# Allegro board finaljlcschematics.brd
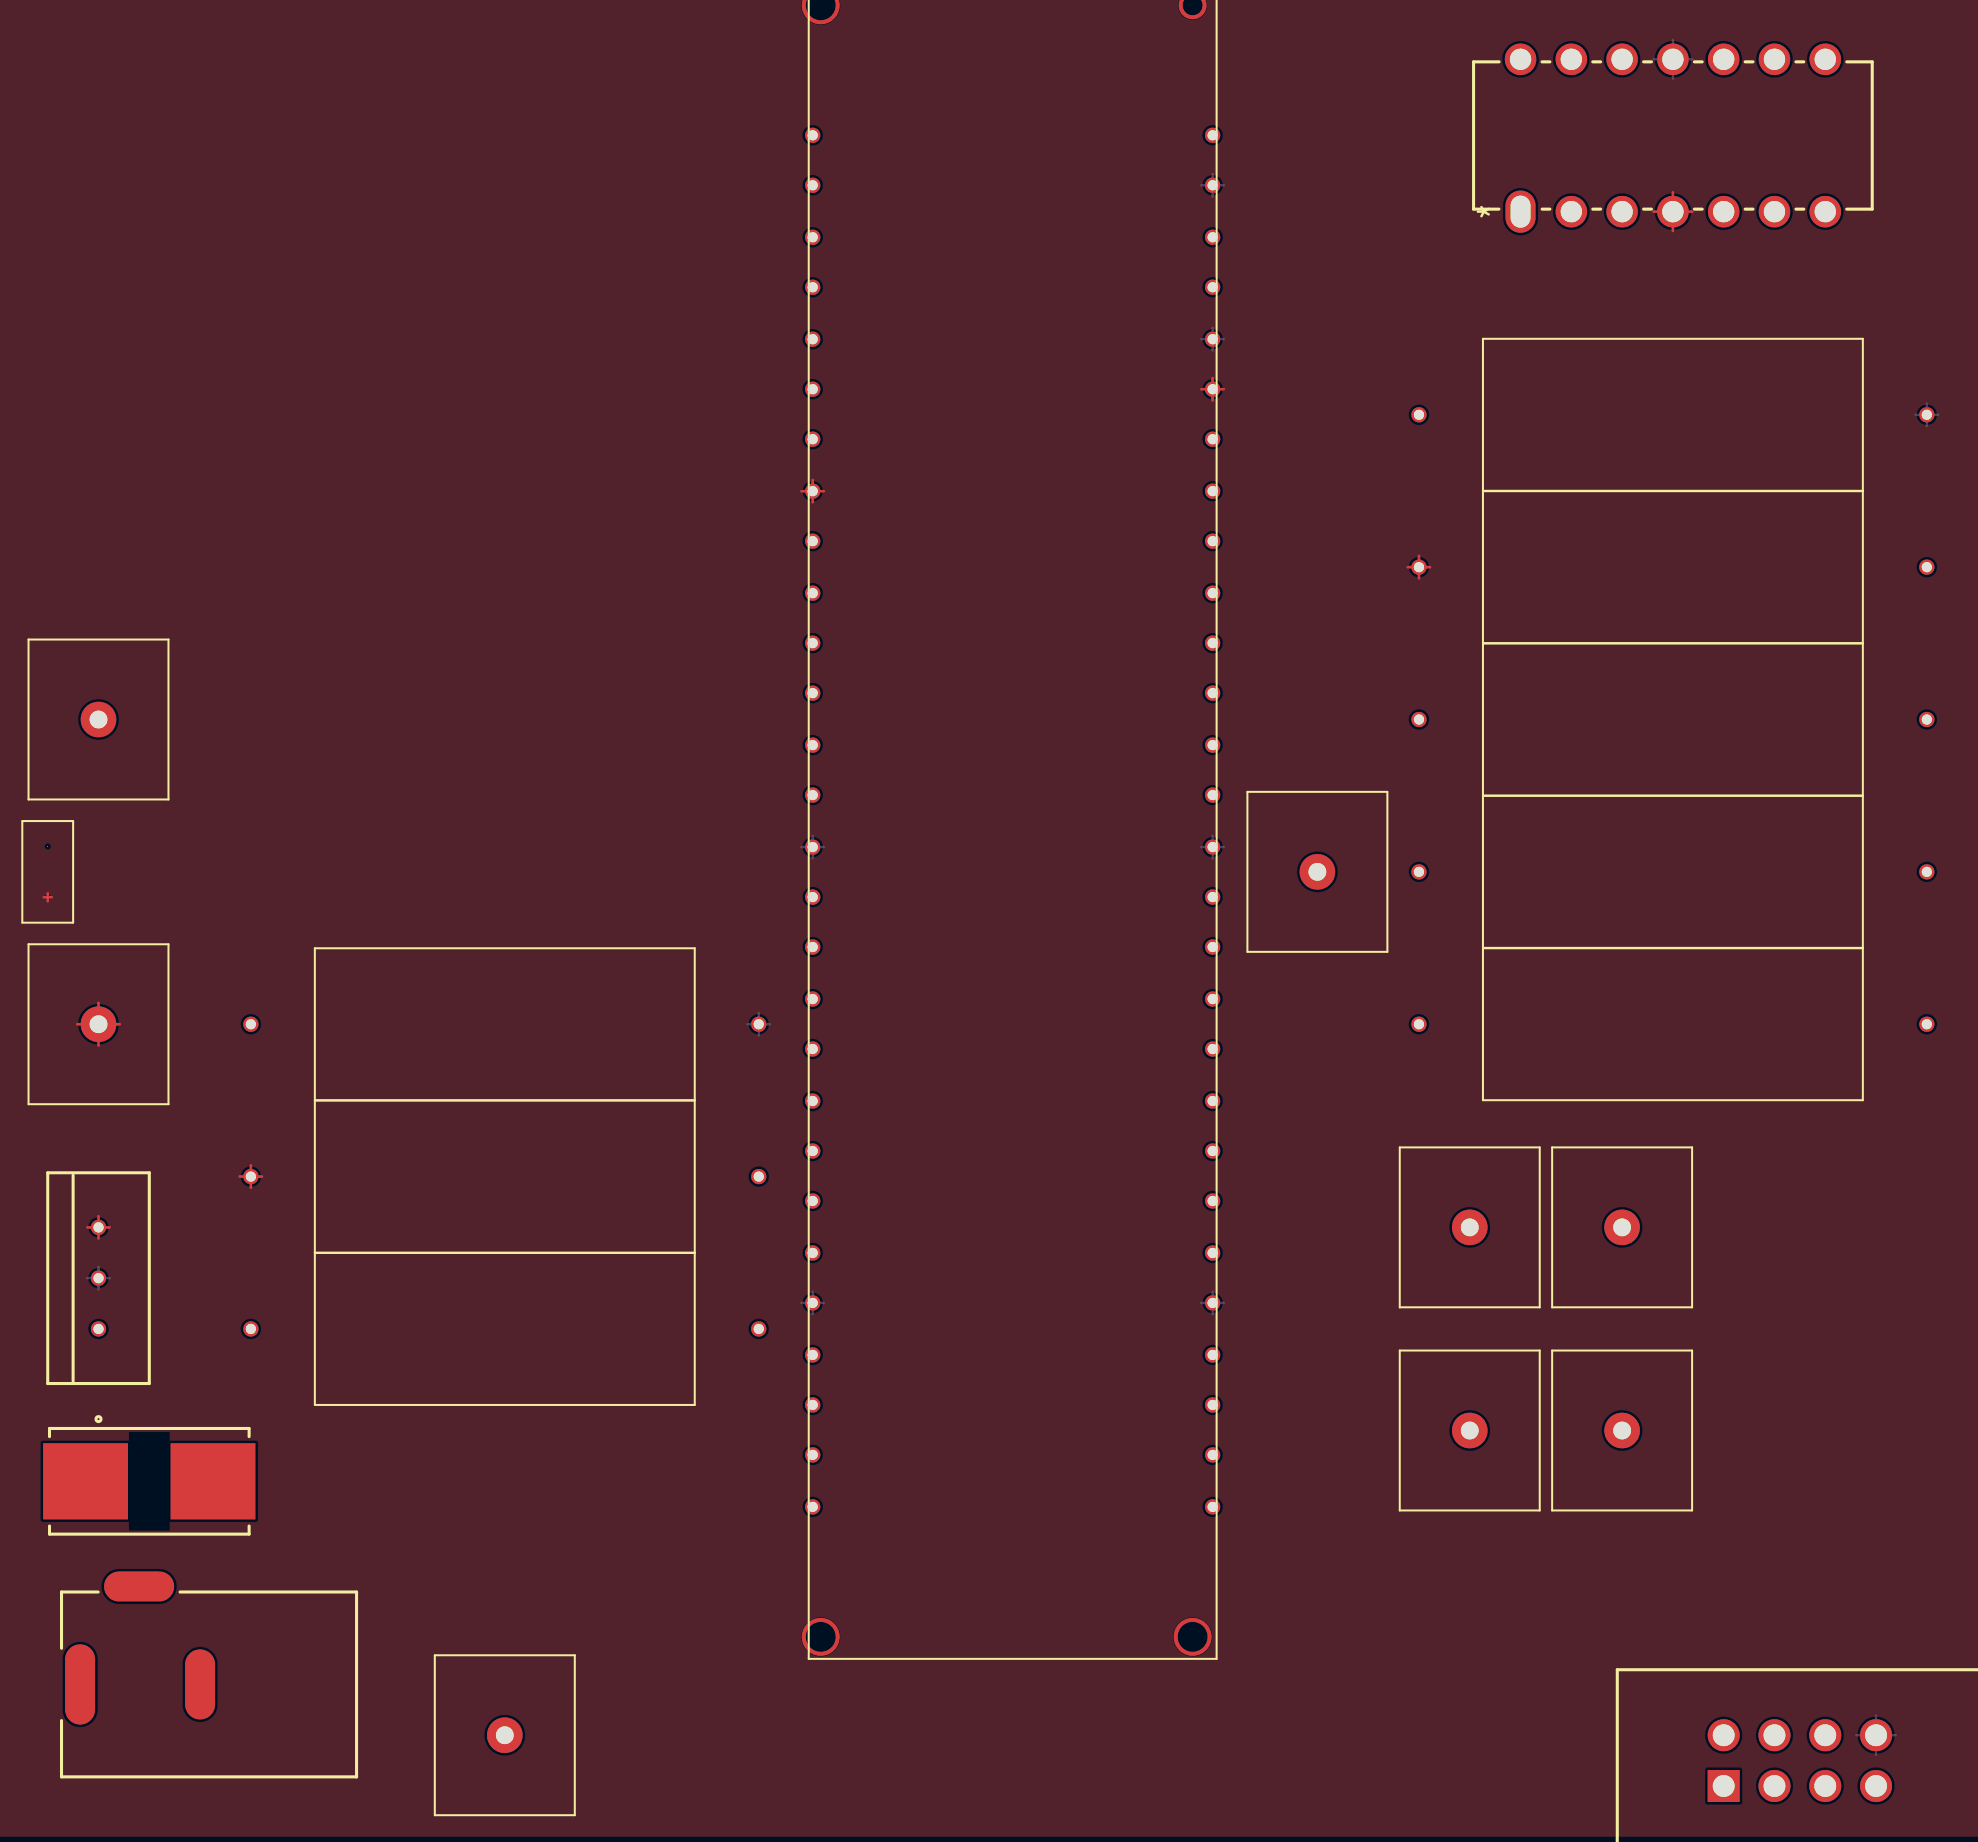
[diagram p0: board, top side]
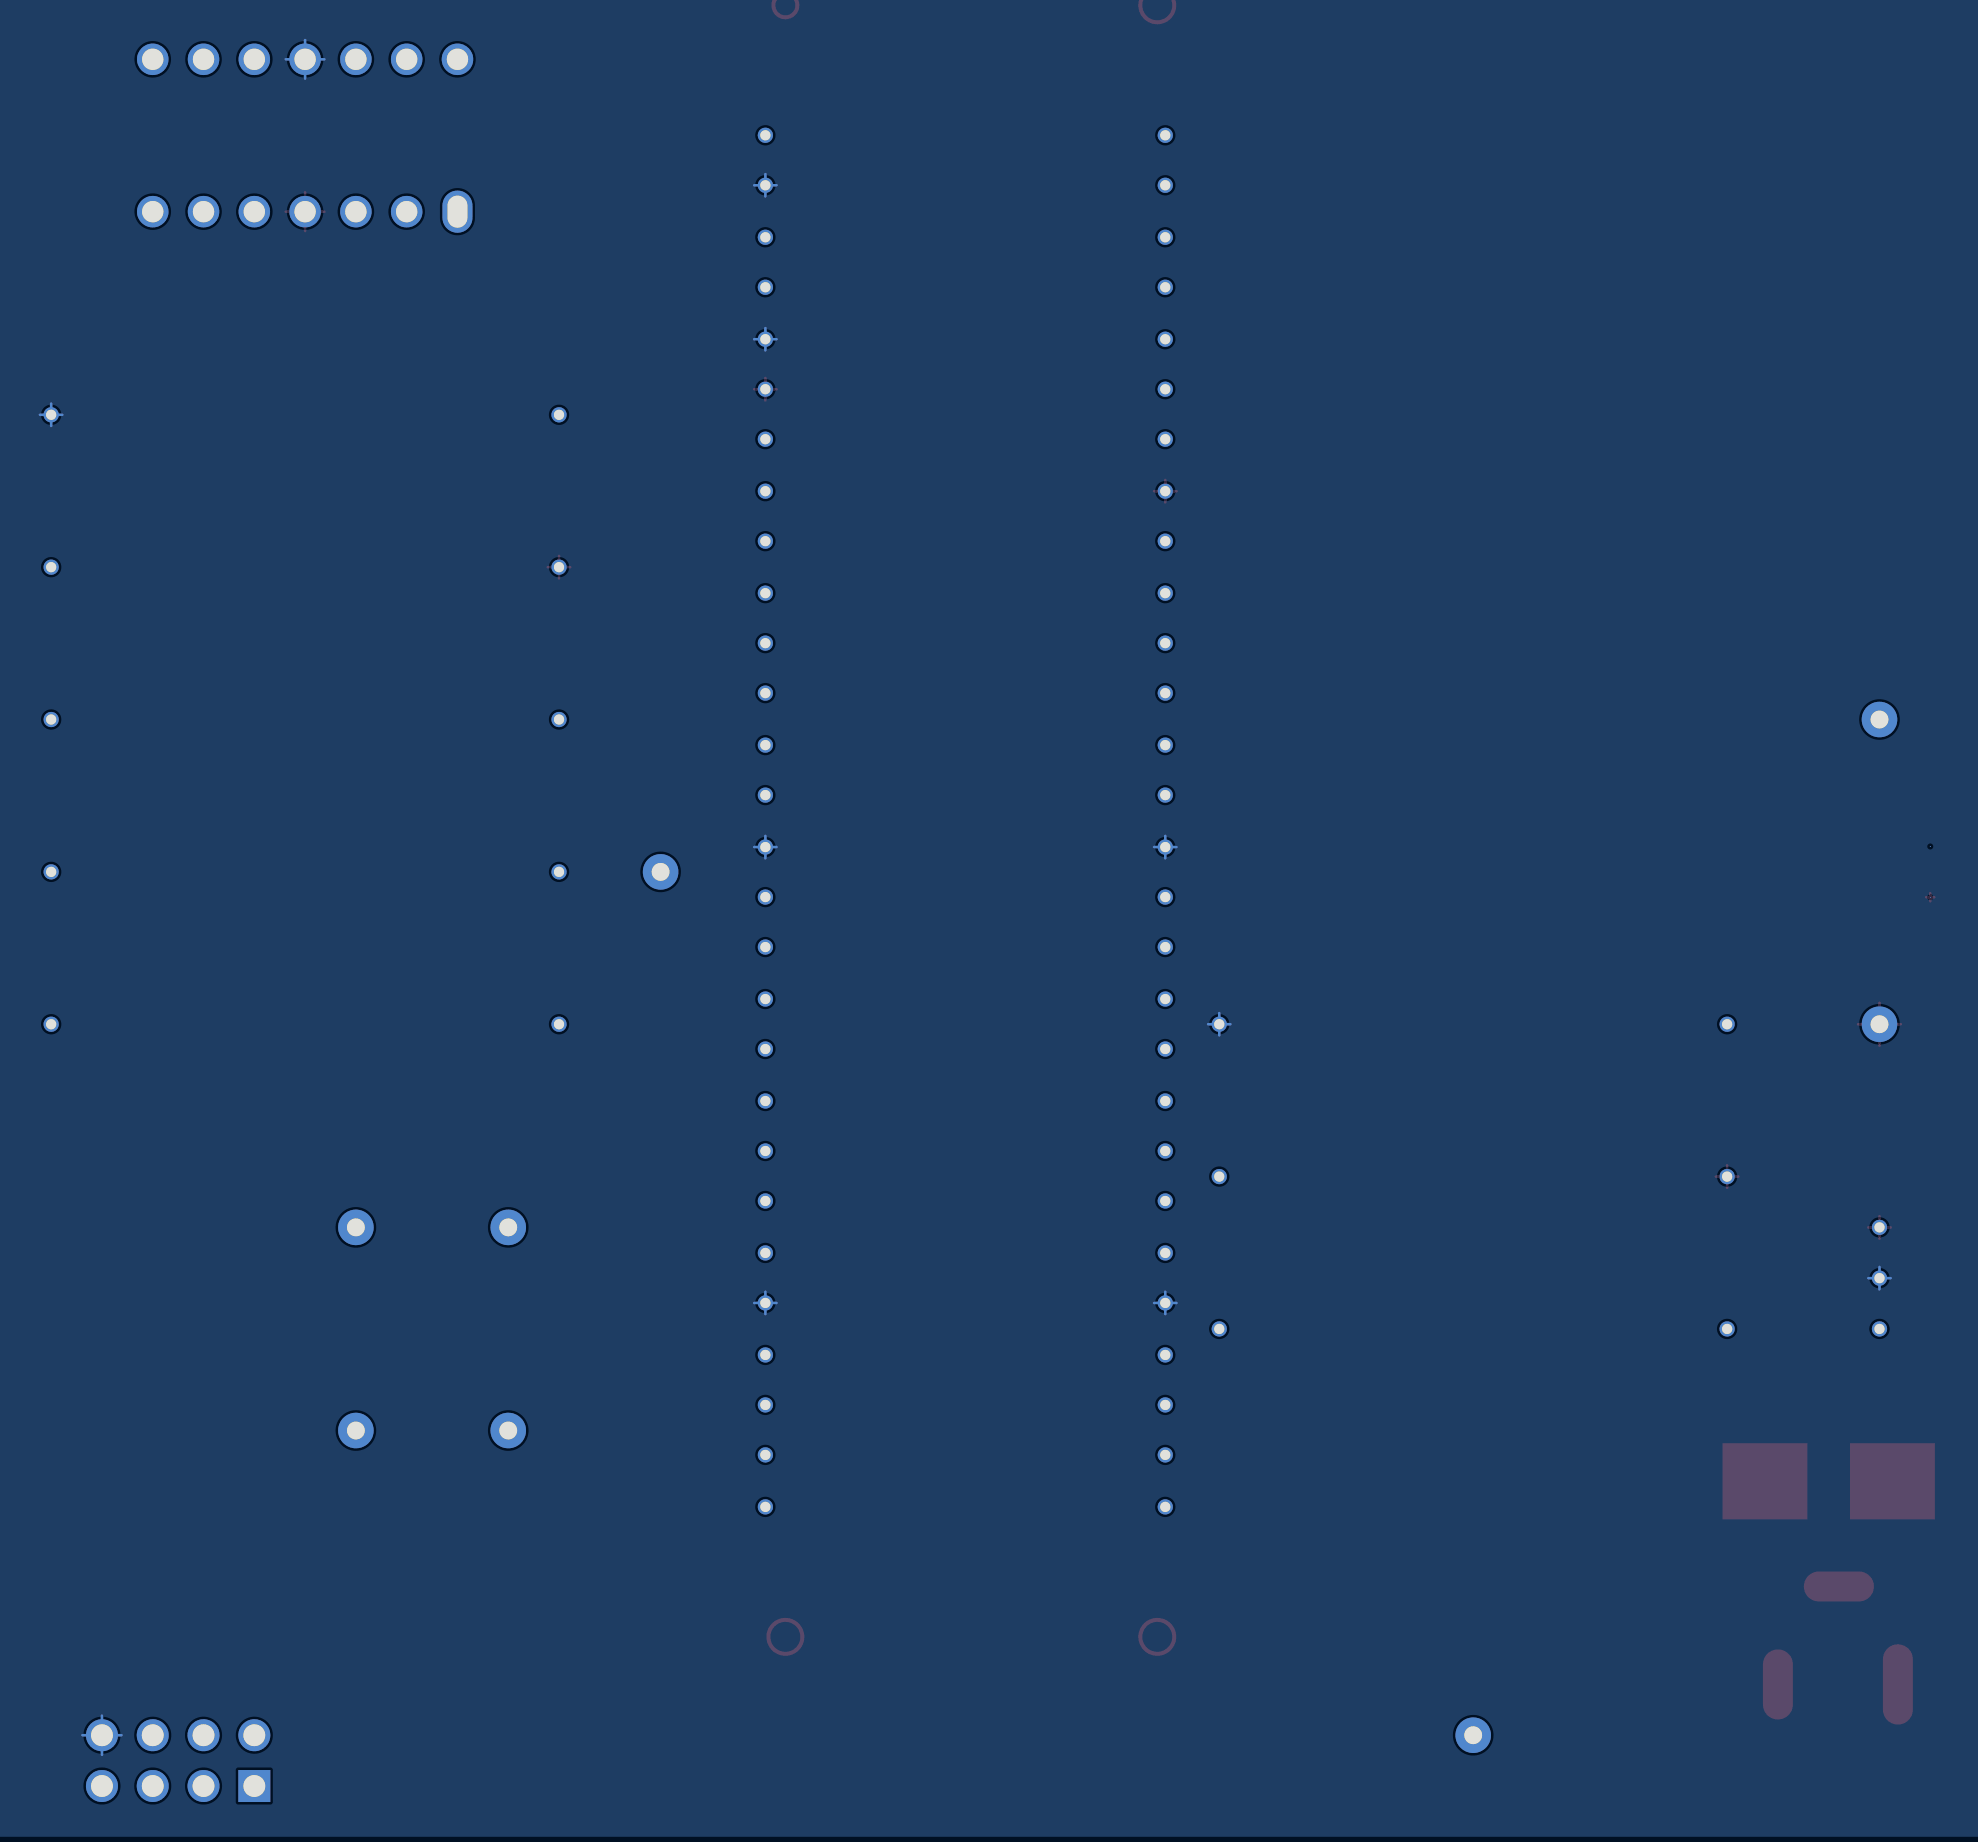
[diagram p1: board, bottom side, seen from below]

No outline. copper layers: TOP, BOTTOM. Coordinates in mm from the lowest, leftmost part position.

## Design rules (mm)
constraint set DEFAULT: min track width 0.127

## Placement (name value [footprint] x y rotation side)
C10  0.1  [RESISTOR_TH]  22.86 22.86 180 top
C11  CAP  [RESISTOR_TH]  22.86 30.48 180 top
F2  FUSE 1.5A  [FUSE_01550900M_LTF]  5.08 15.24 0 top
J22  TestPoint1  [CONNECTORONEPIN]  22.86 2.54 0 top
J23  TestPoint2  [CONNECTORONEPIN]  2.54 38.1 0 top
J25  TestPoint3  [CONNECTORONEPIN]  2.54 53.34 0 top
J27  TestPoint3  [CONNECTORONEPIN]  63.5 45.72 0 top
J29  SpareGPIO1  [CONNECTORONEPIN]  71.12 27.94 0 top
J30  SpareGPIO2  [CONNECTORONEPIN]  71.12 17.78 0 top
J31  SpareGPIO3  [CONNECTORONEPIN]  78.74 27.94 0 top
J32  SpareGPIO4  [CONNECTORONEPIN]  78.74 17.78 0 top
J34  CONN PCB 8_LS  [CONN_61200821621_WRE]  83.82 0 0 top
J35  B_JACK  [NEB21R_LMB]  7.62 5.08 180 top
PCND3  PIC18F57Q43 Curiosity Nano_LS  [56PINS-PIC]  48.26 48.26 0 top
R8  10k  [RESISTOR_TH]  22.86 38.1 0 top
R9  10k  [RESISTOR_TH]  81.28 38.1 0 top
R10  10k  [RESISTOR_TH]  81.28 45.72 0 top
R11  RESISTOR  [RESISTOR_TH]  81.28 53.34 0 top
R12  10k  [RESISTOR_TH]  81.28 60.96 0 top
R13  10k  [RESISTOR_TH]  81.28 68.58 0 top
U11  VR_LS  [TO220-3_ONS]  2.54 22.86 90 top
U12  10kOhms-20kOhms  [HDR_1X02_2]  0 45.72 0 top
U14  MCP6004  [SOIC14-N_MC_MCH]  73.66 78.74 90 top

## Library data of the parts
C10 C11 = MKP1839410084HQ
F2 = FUSE/SM: User Part Number: PN; Tolerance: TOL
J22 J23 J25 J27 J29-J32 = CON1
J34 = CONN PCB 8_2: User Part Number: PN; Tolerance: TOL
J35 = B_JACK: User Part Number: PN; Tolerance: TOL
PCND3 = PIC18F57Q10_18
R8-R13 = RESISTOR
U11 = VR_LS_11: User Part Number: PN; Tolerance: TOL
U12 = FLEX_SENSOR_FS_L_095_103_RH_0
U14 = MCP6004_0: User Part Number: PN; Tolerance: TOL

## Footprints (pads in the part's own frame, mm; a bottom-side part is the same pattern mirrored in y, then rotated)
56PINS-PIC
  round 0.762 hole 0.508: 1(-10,34.3) 2(-10,31.8) 3(-10,29.2) 4(-10,26.7) 5(-10,24.1) 6(-10,21.6) 7(-10,19.1) 8(-10,16.5) 9(-10,14) 10(-10,11.4) 11(-10,8.9) 12(-10,6.4) 13(-10,3.8) 14(-10,1.3) 15(-10,-1.3) 16(-10,-3.8) 17(-10,-6.3) 18(-10,-8.9) 19(-10,-11.4) 20(-10,-14) 21(-10,-16.5) 22(-10,-19) 23(-10,-21.6) 24(-10,-24.1) 25(-10,-26.7) 26(-10,-29.2) 27(-10,-31.7) 28(-10,-34.3) 29(10,-34.3) 30(10,-31.7) 31(10,-29.2) 32(10,-26.7) 33(10,-24.1) 34(10,-21.6) 35(10,-19) 36(10,-16.5) 37(10,-14) 38(10,-11.4) 39(10,-8.9) 40(10,-6.3) 41(10,-3.8) 42(10,-1.3) 43(10,1.3) 44(10,3.8) 45(10,6.4) 46(10,8.9) 47(10,11.4) 48(10,14) 49(10,16.5) 50(10,19.1) 51(10,21.6) 52(10,24.1) 53(10,26.7) 54(10,29.2) 55(10,31.8) 56(10,34.3)
CONN_61200821621_WRE
  rect 1.6x1.6 hole 1.092: 1(0,0)
  round 1.6 hole 1.092: 2(0,2.54) 3(2.54,0) 4(2.54,2.54) 5(5.08,0) 6(5.08,2.54) 7(7.62,0) 8(7.62,2.54)
CONNECTORONEPIN
  round 1.778 hole 0.889: 1(0,0)
FUSE_01550900M_LTF
  rect 4.242x3.81 smd: 1(-3.188,0) 2(3.188,0)
HDR_1X02_2
  round 0.046 hole 0.025: 1(0,1.27) 2(0,-1.27)
NEB21R_LMB
  oval 1.499x3.505 smd: 1(0,0)
  oval 1.499x4.013 smd: 2(6,0)
  oval 3.505x1.499 smd: 3(3.05,-4.9)
RESISTOR_TH
  round 0.762 hole 0.508: 1(-12.7,0) 2(12.7,0)
SOIC14-N_MC_MCH
  oval 2.108x1.499 hole 1.6x0.991: 1(0,0)
  round 1.575 hole 1.067: 2(0,-2.54) 3(0,-5.08) 4(0,-7.62) 5(0,-10.16) 6(0,-12.7) 7(0,-15.24) 8(7.62,-15.24) 9(7.62,-12.7) 10(7.62,-10.16) 11(7.62,-7.62) 12(7.62,-5.08) 13(7.62,-2.54) 14(7.62,0)
TO220-3_ONS
  round 0.762 hole 0.508: 1(0,0) 2(2.54,0) 3(5.08,0)

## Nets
5V: C11.2 J23.1 PCND3.8 PCND3.51(VTG) R12.1 U11.3(VOUT) U12.2(VIN) U14.4
GND: J34.8 J35.2 PCND3.15 PCND3.24 PCND3.33 PCND3.42 PCND3.52 PCND3.55 R8.2 R13.2 U11.2 U14.11(VSS)
FLEX_SENSOR_READINGS: PCND3.43 R11.1 U14.1
LED: PCND3.16
PIN_2: J34.2 PCND3.44
PIN_3: J34.3 PCND3.9
PIN_5: J34.5 PCND3.11
PIN_6: J34.6 PCND3.45
STRAIN_OUT_RAW: J25.1 R8.1 U12.1 U14.12
N106824: C10.2 F2.2 J22.1 U11.1
N106956: C10.1 C11.1
N108303: R9.1 U14.13
N108331: R9.2 R10.1 U14.14
N108415: J27.1 R10.2 R11.2 U14.2
N108457: R12.2 R13.1 U14.3
N113032: J30.1 PCND3.35
N114337: J31.1 PCND3.32
N114341: J32.1 PCND3.29
N122941: F2.1 J35.1
N11281237: J29.1 PCND3.38

Pads without a net: J34 1 4 7; J35 3; PCND3 1 2 3 4 5 6 7 10 12 13 14 17 18 19 20 21 22 23 25 26 27 28 30 31 34 36 37 39 40 41 46 47 48 49 50 53 54 56; U14 5 6 7 8 9 10

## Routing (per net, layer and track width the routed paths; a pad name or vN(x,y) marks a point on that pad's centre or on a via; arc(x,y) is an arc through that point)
5V: length 20.1
  TOP w0.127: J23.1 2.54,39.17 ; J23.1 1.47,38.1 ; J23.1 3.61,38.1 ; J23.1 2.54,37.03 ; 10.16,29.92 C11.2 ; C11.2 10.72,30.48 ; C11.2 10.16,31.04 ; C11.2 9.6,30.48 ; 68.02,60.96 R12.1 ; R12.1 68.58,61.52 ; R12.1 68.58,60.4 ; R12.1 69.14,60.96 ; PCND3.51 58.26,70.42 ; PCND3.51 58.82,69.86 ; PCND3.51 57.7,69.86 ; PCND3.51 58.26,69.3 ; 80.31,78.74 U14.4 ; U14.4 82.25,78.74 ; U14.4 81.28,79.71 ; U14.4 81.28,77.77 ; U11.3 2.54,28.5 ; U11.3 1.98,27.94 ; U11.3 3.1,27.94 ; U11.3 2.54,27.38 ; U12.2 0,44.65 ; U12.2 -0.2,44.45 ; U12.2 0.2,44.45 ; U12.2 0,44.25 ; PCND3.8 38.26,65.32 ; PCND3.8 37.7,64.76 ; PCND3.8 38.82,64.76 ; PCND3.8 38.26,64.2
GND: length 27.9
  BOTTOM w0.127: 37.7,24.16 PCND3.24 ; PCND3.24 38.26,23.6 ; PCND3.24 38.26,24.72 ; PCND3.24 38.82,24.16 ; R13.2 94.54,68.58 ; R13.2 93.98,68.02 ; R13.2 93.42,68.58 ; R13.2 93.98,69.14 ; 38.26,46.4 PCND3.15 ; PCND3.15 38.26,47.52 ; PCND3.15 37.7,46.96 ; PCND3.15 38.82,46.96 ; 57.7,80.06 PCND3.55 ; PCND3.55 58.26,80.62 ; PCND3.55 58.82,80.06 ; PCND3.55 58.26,79.5 ; 35,38.1 R8.2 ; R8.2 35.56,37.54 ; R8.2 36.12,38.1 ; R8.2 35.56,38.66 ; PCND3.42 58.26,47.52 ; PCND3.42 57.7,46.96 ; PCND3.42 58.82,46.96 ; PCND3.42 58.26,46.4 ; 57.7,24.16 PCND3.33 ; PCND3.33 58.26,23.6 ; PCND3.33 58.26,24.72 ; PCND3.33 58.82,24.16 ; U11.2 2.54,25.96 ; U11.2 1.98,25.4 ; U11.2 2.54,24.84 ; U11.2 3.1,25.4 ; PCND3.52 58.82,72.36 ; PCND3.52 58.26,72.92 ; PCND3.52 57.7,72.36 ; PCND3.52 58.26,71.8 ; J34.8 92.42,2.54 ; J34.8 90.46,2.54 ; J34.8 91.44,1.56 ; J34.8 91.44,3.52 ; U14.11 82.25,86.36 ; U14.11 81.28,87.33 ; U14.11 80.31,86.36 ; U14.11 81.28,85.39

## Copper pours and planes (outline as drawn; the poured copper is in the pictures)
5V on TOP: 97.15,-2.54 97.15,97.79 -3.18,97.79 -3.18,-2.54
GND on BOTTOM: 97.15,-2.54 97.15,97.79 -3.18,97.79 -3.18,-2.54
